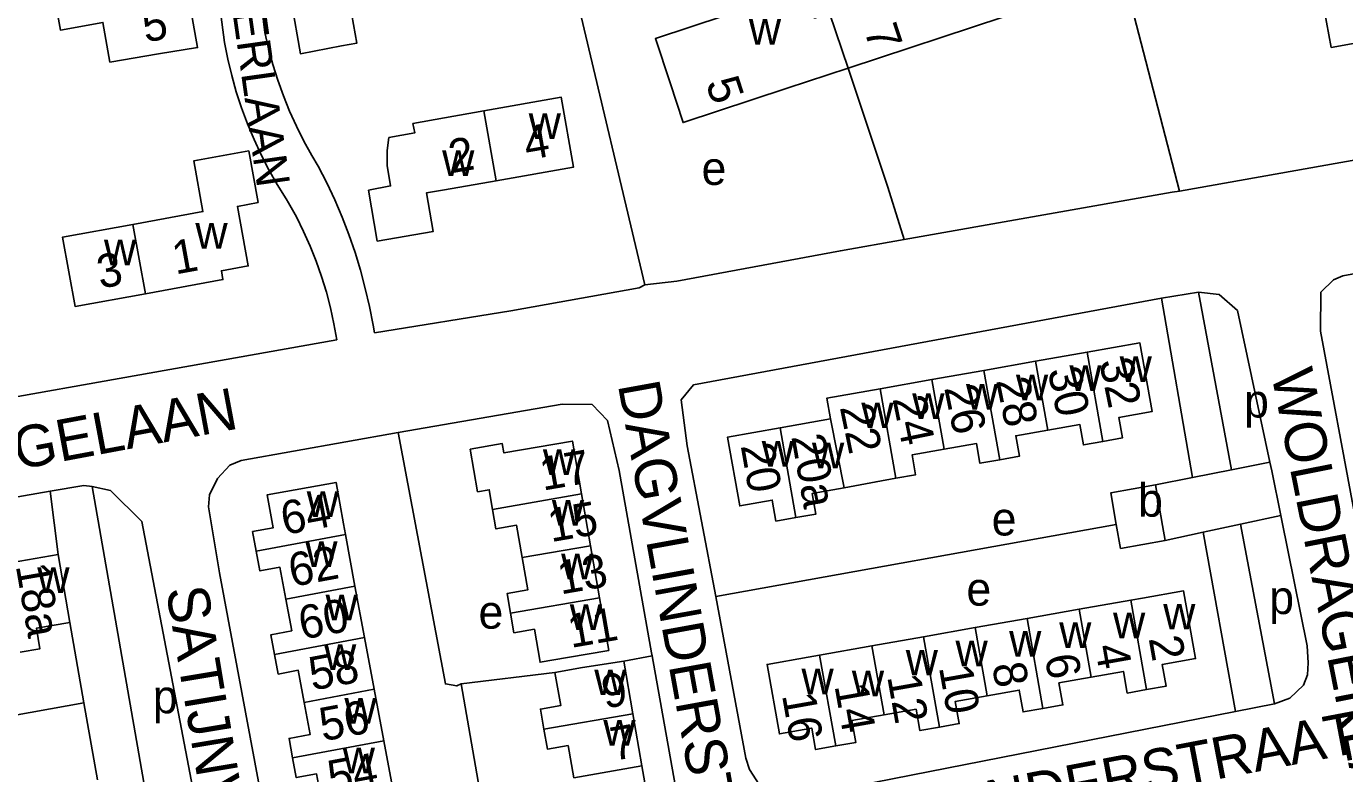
# Model space of a CAD drawing. Extents: x 162883 to 165538, y 383986 to 385172.
# Drawn here: x 163949.9 to 164107.9, y 384654.8 to 384744.4 of the extents above; entities that cross this region are included whole.
import ezdxf

# ---------------------------------------------------------------- set-up
doc = ezdxf.new("R2010")
doc.units = 0
for name, color, linetype in [('BLT_Basislijn', 7, 'Continuous'), ('BLT_Bebouwing', 7, 'Continuous'), ('BLT_Centroide', 7, 'Continuous'), ('BLT_Huisnummer', 7, 'Continuous'), ('BLT_Huisnummer_ tussenligend', 7, 'Continuous'), ('BLT_Onderverdeling_panden', 7, 'Continuous'), ('BLT_Straatnaam', 7, 'Continuous'), ('BLT_Straatnaam_verkleind', 7, 'Continuous')]:
    doc.layers.add(name, color=color, linetype=linetype)

msp = doc.modelspace()

# ---------------------------------------------------------------- linework, layer by layer
at = {"layer": 'BLT_Basislijn'}
for p, q in [((163974.61, 384774.98), (163978.46, 384743.65)), ((163969.74, 384771.82), (163973.6, 384742.44)), ((164015.31, 384750.16), (164024.02, 384713.41)), ((164081.63, 384749.74), (164088.15, 384724.64)), ((164088.15, 384724.64), (164087.26, 384724.49)), ((164087.26, 384724.49), (164055.1, 384718.82)), ((164090.39, 384712.51), (164085.97, 384711.8)), ((164090.39, 384712.51), (164094.36, 384691.22)), ((164085.97, 384711.8), (164089.69, 384690.29)), ((164094.36, 384691.22), (164098.98, 384692.13)), ((164085.24, 384689.41), (164089.69, 384690.29)), ((164089.69, 384690.29), (164094.36, 384691.22)), ((163900.32, 384679.52), (163952.7, 384688.67)), ((163953.65, 384681.07), (163952.7, 384688.67)), ((163957.74, 384689.23), (163966.19, 384640.89)), ((164100.28, 384685.75), (164095.45, 384684.71)), ((164032.52, 384676.06), (164080.55, 384684.67)), ((164090.97, 384683.74), (164086.42, 384682.76)), ((164095.45, 384684.71), (164090.97, 384683.74)), ((164094.85, 384662.25), (164090.97, 384683.74)), ((164095.45, 384684.71), (164099.54, 384663.18)), ((163956.75, 384663.31), (163955.06, 384672.92)), ((164021.49, 384668.31), (164024.89, 384668.93)), ((164030.56, 384637.4), (164024.89, 384668.93)), ((164013.24, 384666.95), (164001.99, 384665.56)), ((163904.83, 384654.01), (163956.75, 384663.31)), ((163958.38, 384654.07), (163956.75, 384663.31)), ((164099.54, 384663.18), (164094.85, 384662.25))]:
    msp.add_line(p, q, dxfattribs=at)
for points in [[(164095.97, 384842.34), (164093.47, 384839.82), (164090.83, 384834.95), (164089.67, 384829.38), (164089.81, 384824.45), (164090.64, 384821.59), (164101.2, 384802.81), (164103.99, 384793.49), (164113.36, 384750.3), (164117.16, 384729.76), (164088.15, 384724.64)], [(163978.46, 384743.65), (163978.9, 384741.72), (163979.42, 384739.8), (163980.01, 384737.91), (163980.68, 384736.04), (163981.42, 384734.2), (163982.24, 384732.4), (163983.13, 384730.62), (163984.09, 384728.89), (163984.85, 384727.61)], [(163973.6, 384742.44), (163974, 384740.45), (163974.48, 384738.48), (163975.03, 384736.53), (163975.67, 384734.6), (163976.37, 384732.7), (163977.15, 384730.83), (163978.01, 384728.99), (163978.93, 384727.18), (163979.93, 384725.42), (163981, 384723.69), (163981.29, 384723.24)], [(164048.41, 384739.37), (164053.17, 384725.12), (164055.1, 384718.82)], [(163984.85, 384727.61), (163985.88, 384725.61), (163986.84, 384723.58), (163987.72, 384721.51), (163988.53, 384719.42), (163989.27, 384717.29), (163989.92, 384715.14), (163990.5, 384712.97), (163991.01, 384710.78), (163991.43, 384708.57), (163991.59, 384707.64)], [(163981.29, 384723.24), (163982.23, 384721.54), (163983.1, 384719.8), (163983.89, 384718.02), (163984.62, 384716.22), (163985.26, 384714.38), (163985.83, 384712.52), (163986.33, 384710.64), (163986.74, 384708.74), (163987.09, 384706.8)], [(164024.02, 384713.41), (164027.84, 384713.85), (164047.46, 384717.48), (164055.1, 384718.82)], [(164113.19, 384664.11), (164113.12, 384664.52), (164105.02, 384707.84), (164105.09, 384712.51), (164106.61, 384713.98), (164107.73, 384714.46), (164127.69, 384718.14)], [(163991.59, 384707.64), (164007.94, 384710.28), (164023.34, 384713.05), (164024.02, 384713.41)], [(164098.98, 384692.13), (164095.1, 384710.32), (164092.89, 384712.22), (164090.39, 384712.51)], [(164032.52, 384676.06), (164029.09, 384694.1), (164028.38, 384699.62), (164029.85, 384701.41), (164085.97, 384711.8)], [(163987.09, 384706.8), (163920.88, 384695.07), (163920.56, 384695.23), (163919.98, 384699.28), (163922.09, 384701.22), (163921.94, 384704.09)], [(163994.45, 384695.69), (164014.12, 384699.09), (164017.7, 384699.06), (164019.53, 384697.12), (164020.92, 384691.14), (164024.83, 384669.29), (164024.89, 384668.93)], [(163994.45, 384695.69), (163975.63, 384692.33), (163974.26, 384691.8), (163972.78, 384690.17), (163971.82, 384688.24), (163971.71, 384686.81), (163973.03, 384678.88), (163980.94, 384636.5), (163981.07, 384635.82)], [(164001.99, 384665.56), (164001.46, 384665.32), (164000.1, 384665.56), (163994.45, 384695.69)], [(164100.28, 384685.75), (164099.19, 384691.11), (164098.98, 384692.13)], [(163957.74, 384689.23), (163956.76, 384689.36), (163952.7, 384688.67)], [(163957.74, 384689.23), (163959.94, 384688.75), (163963.69, 384685.03), (163970.64, 384648.63), (163970.57, 384645.51), (163969.74, 384643.96), (163968.69, 384642.3), (163966.19, 384640.89)], [(164099.54, 384663.18), (164101.36, 384663.87), (164102.98, 384665.4), (164103.46, 384666.66), (164103.56, 384668.09), (164103.43, 384670.14), (164100.36, 384685.35), (164100.28, 384685.75)], [(164032.52, 384676.06), (164036.11, 384656.65), (164036.56, 384655.3), (164037.73, 384653.52), (164039.89, 384652.19), (164042.92, 384652.09), (164094.85, 384662.25)], [(164001.99, 384665.56), (164006.35, 384640.57), (164006.46, 384640.01)]]:
    msp.add_lwpolyline(points, dxfattribs=at)
at = {"layer": 'BLT_Bebouwing'}
for p, q in [((164067.07, 384745.51), (164048.41, 384739.37)), ((164048.41, 384739.37), (164041.09, 384736.96)), ((164004.72, 384734.24), (164000, 384733.42)), ((164000, 384733.42), (163996.21, 384732.75)), ((163977.66, 384723.25), (163976.53, 384729.45)), ((163990.86, 384724.74), (163991.93, 384718.62)), ((164070.88, 384704.23), (164064.68, 384703.14)), ((164077.06, 384705.33), (164070.88, 384704.23)), ((164064.68, 384703.14), (164058.45, 384702.04)), ((164058.45, 384702.04), (164052.22, 384700.94)), ((164046.27, 384697.32), (164040.23, 384696.25)), ((164017.5, 384682.12), (164016.43, 384688.34)), ((163988.11, 384683.46), (163989.26, 384677.29)), ((164018.58, 384675.9), (164017.5, 384682.12)), ((163953.65, 384681.07), (163947.25, 384679.96)), ((163955.06, 384672.92), (163953.65, 384681.07)), ((163989.26, 384677.29), (163990.41, 384671.12)), ((164076.1, 384674.51), (164082.3, 384675.61)), ((164069.85, 384673.41), (164076.1, 384674.51)), ((164063.63, 384672.31), (164069.85, 384673.41)), ((163990.41, 384671.12), (163991.56, 384664.92)), ((164051.24, 384670.12), (164057.44, 384671.22)), ((164057.44, 384671.22), (164063.63, 384672.31)), ((164044.98, 384669.01), (164051.24, 384670.12)), ((164022.59, 384662), (164021.49, 384668.31)), ((163991.56, 384664.92), (163992.72, 384658.73)), ((164023.67, 384655.75), (164022.59, 384662)), ((163992.72, 384658.73), (163993.87, 384652.55)), ((164024.75, 384649.54), (164023.67, 384655.75))]:
    msp.add_line(p, q, dxfattribs=at)
for points in [[(163997.44, 384748.41), (163988.68, 384746.85), (163989.47, 384742.34), (163987.65, 384742.03), (163982.71, 384741.09), (163981.63, 384747.23), (163982.88, 384747.45), (163981.77, 384753.78)], [(163952.76, 384750.55), (163953.93, 384743.93), (163959.03, 384744.84), (163959.87, 384740.1), (163965.71, 384741.07), (163970.39, 384741.83), (163969.03, 384749.5), (163961.37, 384748.15), (163960.73, 384751.96)], [(164108.94, 384750), (164109.14, 384748.81), (164111.8, 384749.3), (164112.94, 384743.05), (164106.32, 384741.84), (164105.2, 384747.94), (164096.89, 384746.43)], [(164037.78, 384747.02), (164025.29, 384742.91), (164027.04, 384737.6), (164028.6, 384732.85), (164041.09, 384736.96)], [(164006.2, 384725.87), (164015.46, 384727.49), (164014, 384735.88), (164004.72, 384734.24)], [(163996.21, 384732.75), (163996.42, 384731.61), (163993.31, 384731.06)], [(163993.31, 384731.06), (163993.11, 384729.5), (163993.1, 384727.67), (163993.39, 384726.03), (163993.52, 384725.25), (163990.86, 384724.74)], [(163976.53, 384729.45), (163969.92, 384728.25), (163971.02, 384722.17), (163962.61, 384720.64)], [(163991.93, 384718.62), (163998.64, 384719.8), (163997.83, 384724.41), (164000, 384724.79), (164006.2, 384725.87)], [(163964.12, 384712.33), (163973.43, 384714.02), (163973.24, 384715.09), (163976.47, 384715.67), (163975.17, 384722.8), (163977.66, 384723.25)], [(163962.61, 384720.64), (163954.19, 384719.11), (163955.7, 384710.8), (163964.12, 384712.33)], [(164078.95, 384694.64), (164081.29, 384695.05), (164080.86, 384697.5), (164084.85, 384698.21), (164083.39, 384706.44), (164077.06, 384705.33)], [(164052.22, 384700.94), (164045.83, 384699.81), (164046.27, 384697.32)], [(164040.23, 384696.25), (164033.94, 384695.14), (164035.4, 384686.9), (164039.3, 384687.59), (164039.74, 384685.09), (164042.13, 384685.51)], [(164078.95, 384694.64), (164076.61, 384694.22), (164076.18, 384696.65), (164072.34, 384695.98)], [(164016.43, 384688.34), (164015.33, 384694.67), (164007.11, 384693.25), (164006.92, 384694.37), (164003.08, 384693.7), (164003.97, 384688.6), (164005.35, 384688.84), (164005.75, 384686.49)], [(164072.34, 384695.98), (164068.5, 384695.3), (164068.93, 384692.86), (164066.57, 384692.44)], [(164059.93, 384693.69), (164056.07, 384693.01), (164056.48, 384690.64), (164054.11, 384690.22)], [(164066.57, 384692.44), (164064.2, 384692.02), (164063.79, 384694.37), (164059.93, 384693.69)], [(164054.11, 384690.22), (164051.75, 384689.8), (164047.9, 384689.06)], [(163977.42, 384681.47), (163976.98, 384683.83), (163979.46, 384684.29), (163978.73, 384688.23), (163987, 384689.72), (163987.87, 384684.76), (163988.11, 384683.46)], [(164042.13, 384685.51), (164044.53, 384685.93), (164044.09, 384688.39), (164047.9, 384689.06)], [(164085.24, 384689.41), (164079.88, 384688.46), (164080.55, 384684.67)], [(164086.42, 384682.76), (164086.1, 384684.57), (164085.24, 384689.41)], [(164005.75, 384686.49), (164006.16, 384684.15), (164008.64, 384684.58), (164009.31, 384680.7)], [(164080.55, 384684.67), (164081.06, 384681.81), (164086.42, 384682.76)], [(163980.96, 384675.74), (163980.25, 384679.55), (163977.86, 384679.11), (163977.42, 384681.47)], [(164009.31, 384680.7), (164009.98, 384676.83), (164007.5, 384676.4), (164007.91, 384674.05)], [(163979.61, 384669.11), (163979.17, 384671.47), (163981.67, 384671.94), (163980.96, 384675.74)], [(164007.91, 384674.05), (164008.32, 384671.7), (164010.77, 384672.12), (164011.46, 384668.16), (164014.75, 384668.73), (164019.68, 384669.58), (164018.58, 384675.9)], [(164082.3, 384675.61), (164083.7, 384675.85), (164088.62, 384676.72), (164090.06, 384668.6), (164086.07, 384667.9), (164086.53, 384665.29), (164084.19, 384664.88)], [(163949.09, 384669.37), (163951.47, 384669.78), (163951.05, 384672.23), (163955.06, 384672.92)], [(163983.18, 384663.36), (163982.46, 384667.2), (163980.05, 384666.75), (163979.61, 384669.11)], [(164013.24, 384666.95), (164016.55, 384667.52), (164021.49, 384668.31)], [(164046.9, 384658.13), (164044.49, 384657.7), (164044.04, 384660.27), (164040.15, 384659.58), (164038.68, 384667.9), (164043.61, 384668.77), (164044.98, 384669.01)], [(164011.91, 384660.15), (164011.49, 384662.56), (164013.93, 384662.98), (164013.24, 384666.95)], [(164077.54, 384666.38), (164073.68, 384665.69), (164074.15, 384663.05), (164071.76, 384662.63)], [(164084.19, 384664.88), (164081.86, 384664.46), (164081.4, 384667.06), (164077.54, 384666.38)], [(164071.76, 384662.63), (164069.37, 384662.21), (164068.91, 384664.83), (164065.08, 384664.15)], [(163981.78, 384656.69), (163981.35, 384659.04), (163983.89, 384659.52), (163983.18, 384663.36)], [(164065.08, 384664.15), (164061.24, 384663.47), (164061.71, 384660.82), (164059.36, 384660.4)], [(164052.7, 384661.85), (164048.85, 384661.17), (164049.32, 384658.55), (164046.9, 384658.13)], [(164059.36, 384660.4), (164057, 384659.98), (164056.55, 384662.53), (164052.7, 384661.85)], [(164015.49, 384654.33), (164014.82, 384658.18), (164012.33, 384657.75), (164011.91, 384660.15)], [(163985.36, 384650.97), (163984.65, 384654.79), (163982.22, 384654.34), (163981.78, 384656.69)]]:
    msp.add_lwpolyline(points, dxfattribs=at)
at = {"layer": 'BLT_Onderverdeling_panden'}
for p, q in [((164006.2, 384725.87), (164004.72, 384734.24)), ((163962.61, 384720.64), (163964.12, 384712.33)), ((164072.34, 384695.98), (164070.88, 384704.23)), ((164078.95, 384694.64), (164077.06, 384705.33)), ((164066.57, 384692.44), (164064.68, 384703.14)), ((164054.11, 384690.22), (164052.22, 384700.94)), ((164059.93, 384693.69), (164058.45, 384702.04)), ((164042.13, 384685.51), (164040.23, 384696.25)), ((164046.27, 384697.32), (164047.9, 384689.06)), ((164005.75, 384686.49), (164016.43, 384688.34)), ((163977.42, 384681.47), (163988.11, 384683.46)), ((164009.31, 384680.7), (164017.5, 384682.12)), ((163980.96, 384675.74), (163989.26, 384677.29)), ((164007.91, 384674.05), (164018.58, 384675.9)), ((164084.19, 384664.88), (164082.3, 384675.61)), ((164077.54, 384666.38), (164076.1, 384674.51)), ((164071.76, 384662.63), (164069.85, 384673.41)), ((163979.61, 384669.11), (163990.41, 384671.12)), ((164059.36, 384660.4), (164057.44, 384671.22)), ((164065.08, 384664.15), (164063.63, 384672.31)), ((164052.7, 384661.85), (164051.24, 384670.12)), ((164046.9, 384658.13), (164044.98, 384669.01)), ((163983.18, 384663.36), (163991.56, 384664.92)), ((164011.91, 384660.15), (164022.59, 384662)), ((163981.78, 384656.69), (163992.72, 384658.73)), ((164015.49, 384654.33), (164023.67, 384655.75))]:
    msp.add_line(p, q, dxfattribs=at)
msp.add_lwpolyline([(164043.4, 384748.52), (164044.37, 384745.36), (164046.18, 384745.97), (164048.41, 384739.37)], dxfattribs=at)

# ---------------------------------------------------------------- texts
at = {"layer": 'BLT_Centroide'}
for s, p in [('w', (164036.49, 384742.19)), ('w', (164010.09, 384730.88)), ('w', (163999.71, 384726.44)), ('e', (164030.82, 384725.37)), ('w', (163970.12, 384717.72)), ('w', (163959.16, 384715.72)), ('w', (164080.95, 384701.77)), ('w', (164068.52, 384699.56)), ('w', (164074.92, 384700.69)), ('w', (164062.52, 384698.45)), ('w', (164049.97, 384696.22)), ('w', (164056.08, 384697.31)), ('p', (164095.87, 384697.49)), ('w', (164038.03, 384691.62)), ('w', (164011.8, 384690.59)), ('w', (164044.06, 384691.39)), ('b', (164083.16, 384685.61)), ('w', (163983.47, 384685.59)), ('w', (164012.87, 384684.53)), ('e', (164065.61, 384683.36)), ('w', (163983.3, 384679.59)), ('w', (164013.98, 384678.09)), ('w', (163951.16, 384676.45)), ('e', (164062.58, 384674.95)), ('w', (163985.73, 384673.19)), ('p', (164098.89, 384673.94)), ('e', (164004.07, 384672.19)), ('w', (164015.02, 384672.03)), ('w', (164080.16, 384671.03)), ('w', (164086.17, 384672.09)), ('w', (164073.7, 384669.89)), ('w', (164067.7, 384668.83)), ('w', (163985.55, 384667.25)), ('w', (164055.3, 384666.58)), ('w', (164061.27, 384667.67)), ('w', (164017.95, 384664.22)), ('w', (164042.8, 384664.33)), ('w', (164048.84, 384664.08)), ('p', (163965.02, 384662.05)), ('w', (163987.99, 384660.81)), ('w', (164019.04, 384658.16)), ('w', (163987.78, 384654.84))]:
    msp.add_text(s, height=4, dxfattribs=at).set_placement(p)
at = {"layer": 'BLT_Huisnummer'}
for s, rotation, p in [('5', 10.298, (163964.11, 384742.43)), ('7', 288.1989, (164050.27, 384743.93)), ('5', 288.203, (164031.29, 384737.61)), ('4', 9.7706, (164009.87, 384728.33)), ('2', 9.8739, (164000.86, 384726.77)), ('1', 10.298, (163967.73, 384714.63)), ('3', 10.298, (163958.7, 384712.93)), ('32', 281.6508, (164078.49, 384704.24)), ('26', 281.6508, (164059.9, 384701.06)), ('22', 281.6508, (164047.38, 384698.74)), ('17', 9.8416, (164011.79, 384688.72)), ('20', 280.0171, (164035.5, 384694.12)), ('64', 10.5502, (163980.77, 384683.4)), ('18a', 279.853, (163948.57, 384679.73)), ('11', 9.8416, (164015.15, 384669.87)), ('2', 280.0199, (164084.42, 384671.03)), ('58', 10.5502, (163984.13, 384664.76)), ('6', 280.0253, (164071.96, 384668.85)), ('9', 9.8416, (164019.21, 384662.6)), ('10', 280.0253, (164059.27, 384667.57)), ('16', 280.0253, (164040.45, 384664.23)), ('54', 10.5502, (163986.39, 384652.35))]:
    msp.add_text(s, height=4, rotation=rotation, dxfattribs=at).set_placement(p)
at = {"layer": 'BLT_Huisnummer_ tussenligend'}
for s, rotation, p in [('30', 281.6508, (164072.31, 384703.17)), ('28', 281.6508, (164066.11, 384701.94)), ('24', 281.6508, (164053.7, 384699.76)), ('20a', 280.0272, (164041.57, 384695.22)), ('15', 9.8416, (164012.76, 384682.55)), ('62', 10.5502, (163981.7, 384677.18)), ('13', 9.8416, (164013.92, 384676.28)), ('60', 10.5502, (163982.9, 384670.86)), ('4', 280.0199, (164077.98, 384670.05)), ('8', 280.0253, (164065.64, 384667.84)), ('12', 280.0253, (164053.07, 384666.45)), ('14', 280.0253, (164046.75, 384665.35)), ('56', 10.5502, (163985.39, 384658.68)), ('7', 9.8416, (164020.25, 384656.34))]:
    msp.add_text(s, height=4, rotation=rotation, dxfattribs=at).set_placement(p)
at = {"layer": 'BLT_Straatnaam'}
for s, height, rotation, p in [('APOLLOVLINDERLAAN', 5, 282.4461, (164102.74, 384798.76)), ('WOLDRAGERLAAN', 5, 281.1931, (164099.11, 384702.8)), ('PAGELAAN', 5, 10.5729, (163940.01, 384689.58)), ('DAGVLINDERSTRAAT', 4.9999, 280.278, (164020.77, 384701.44)), ('SATIJNVLINDERLAAN', 5, 279.4364, (163966.58, 384676.92)), ('DAGVLINDERSTRAAT', 5, 10.7734, (164041.38, 384644.37))]:
    msp.add_text(s, height=height, rotation=rotation, dxfattribs=at).set_placement(p)
at = {"layer": 'BLT_Straatnaam_verkleind'}
msp.add_text('CITROENVLINDERLAAN', height=4, rotation=278.0131, dxfattribs=at).set_placement((163969.01, 384785.54))

doc.saveas('drawing.dxf')
